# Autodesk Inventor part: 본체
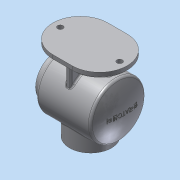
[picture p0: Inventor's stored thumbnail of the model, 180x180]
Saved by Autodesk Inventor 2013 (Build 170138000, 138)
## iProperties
Created: 2016-04
Part Number: 본체
Material: 알루미늄 6061
Document SubType Name: Modeling
Designer: dgall
Density: 2.71 g/cm^3
Mass: 909.634 g
Surface Area: 1226.76 cm^2
Volume: 335.658 cm^3
Author: dgall
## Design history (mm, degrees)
sketch "스케치1"
  geometry: L1 (-61, 0)-(61, 0); L2 (-61, 27)-(-46, 27); L3 (-46, 27)-(-46, 47); L4 (-46, 47)-(48.145, 47); L5 (-61, 27)-(-61, 38); L6 (-61, 38)-(-49, 38); L7 (-49, 38)-(-49, 50); L8 (-49, 50)-(50.087, 50); A1 r 120 centre (-59, 0) between (61, 0) and (50.087, 50); A2 r 117 centre (-59, 0) between (58, 0) and (48.145, 47); 2 further points
  constraints: 16 end point, 4 parallel, 4 point on circle, 3 perpendicular, 2 centre point, 2 point on line, 1 coincident, 1 concentric, 1 horizontal, 1 horizontal alignment, 1 midpoint, 1 vertical alignment
  dimensions: "d0" = 122 distance of L1.end L1.start; "d11" = 54 diameter of L2 L1; "d12" = 76 diameter of L6 L1; "d13" = 100 diameter of L8 L1; "d14" = 94 diameter of L4 L1; "d16" = 3 distance between parallel lines of L3 L7; "d99" = 120 radius of A1; "d101" = 3 distance of L1.end A2.start
revolve "회전1" sketch "스케치1" stored, may be unused: angle "d18" = 90 deg
node "작업 평면1"
sketch "스케치2"
  geometry: L1 (49.544, 50)-(49.544, -50) reference; C1 r 38 at (-0.456, 0); 1 further point
  constraints: 1 centre point, 1 horizontal alignment
  dimensions: "d104" = 50 distance from line of L1 C1.centre; "d105" = 76 diameter of C1
extrude "돌출1" join sketch "스케치2" distance "d23" = 15; taper "d25" = 0 deg; dims "d24" = 30, "d26" = 0
sketch "스케치13"
  geometry: L1 (61, 27)-(61, -27) reference; L2 (46, 47)-(46, -47) reference; L3 (-48.145, -47)-(46, -47) reference; L4 (61, 0)-(-58, 0); L5 (46, 0)-(46, -47); L6 (46, -47)-(-48.145, -47); A1 r 117 centre (59, 0) between (-48.145, 47) and (-48.145, -47) reference; A2 r 117 centre (59, 0) between (-58, 0) and (-48.145, -47); 1 further point
  constraints: 6 end point, 3 point on circle, 2 collinear, 2 midpoint, 1 centre point, 1 concentric, 1 point on line
revolve "회전4" sketch "스케치13" stored, may be unused: angle "d102" = 90 deg
node "작업 평면2"
sketch "스케치5"
  geometry: L1 (-17.5, 50)-(17.5, 50); L2 (-17.5, -50)-(17.5, -50); C1 r 5 at (54, 0); C2 r 5 at (-54, 0); A1 r 50 centre (-17.5, 0) between (-17.5, 50) and (-17.5, -50); A2 r 50 centre (17.5, 0) between (17.5, -50) and (17.5, 50); 1 further point
  constraints: 4 centre point, 4 end point, 4 horizontal alignment, 4 point on circle, 2 equal radius, 2 tangent, 1 horizontal, 1 parallel
  dimensions: "d34" = 135 dimension on A2 A1; "d36" = 50 radius of A1; "d37" = 17.5 distance of point (0, 0) A2.centre; "d38" = 10 diameter of C1; "d39" = 54 distance of point (0, 0) C1.centre; "d40" = 54 distance of C2.centre point (0, 0)
extrude "돌출3" join sketch "스케치5" distance "d41" = 10; taper "d42" = 0 deg
node "작업 평면3"
  node "작업축2"
sketch "스케치6"
  geometry: L1 (-49.544, -50)-(49.544, -50) reference; L2 (-18.044, -69)-(-68.044, -69) reference; L3 (66.956, -69)-(16.956, -69) reference; L4 (16.956, -69)-(-18.044, -69) reference; L5 (-68.044, -79)-(-68.044, -69) reference; L6 (66.956, -79)-(66.956, -69) reference; L7 (-39.544, -69)-(-36.193, -50); L8 (40.456, -69)-(37.106, -50); L9 (38.456, 65)-(-37.544, 65) reference; 1 further point
  constraints: 4 end point, 4 point on line, 1 equal length
  dimensions: "d44" = 39 horizontal distance of point (-0.544, 0) L7.start; "d45" = 41 horizontal distance of L8.start point (-0.544, 0); "d46" = 100 deg angle of L3 L8
sketch "스케치7"
  geometry: L1 (-50, 69)-(50, 69) reference; L2 (-40, 30)-(-40, 69); L3 (40, 30)-(40, 69); A1 r 50 centre (0, 0) between (-40, 30) and (40, 30) reference; 1 further point
  constraints: 4 end point, 2 point on circle, 2 point on line, 1 horizontal alignment, 1 parallel, 1 perpendicular
  dimensions: "d47" = 40 distance from line of point (0, 0) L2
extrude "돌출4" join sketch "스케치7" stored distance "d48" = 10; taper "d49" = 0 deg
feature "리브1" dims "d50" = 1, "d51" = 10, "d52" = 0, "d53" = 0, "d54" = 1, "d55" = 1
feature "리브2" dims "d56" = 1, "d57" = 10, "d58" = 0, "d59" = 0, "d60" = 1, "d61" = 1
chamfer "모따기1" distance "d62" = 3; stored, may be unused: second distance "d63" = 2, angle "d64" = 45 deg
fillet "모깎기3" dims "d65" = 5
fillet "모깎기5" dims "d67" = 2
chamfer "모따기2" distance "d68" = 1; stored, may be unused: second distance "d69" = 2, angle "d70" = 45 deg
sketch "스케치8"
  geometry: C1 r 38 at (0, 0) reference; 1 further point
  constraints: 1 horizontal alignment
  dimensions: "d71" = 32.5 distance of C1.centre point (-32.5, 0)
hole "구멍1" sketch "스케치8" at (-32.5, 0) diameter "d72" = 3.242; stored, may be unused: countersink angle "d76" = 90 deg, drill point angle "d78" = 118 deg; dims "d73" = 8, "d74" = 4, "d75" = 2, "d77" = 10
fillet "모깎기6" dims "d93" = 3
fillet "모깎기7" dims "d94" = 3
fillet "모깎기8" dims "d95" = 3
fillet "모깎기9" dims "d103" = 2
node "작업 평면5"
sketch "스케치15"
  geometry: C1 r 38 at (0, 0) reference; C2 r 27 at (0, 0); 1 further point
  constraints: 1 centre point, 1 concentric
  dimensions: "d106" = 54 diameter of C2
extrude "돌출5" cut sketch "스케치15" distance "d108" = 30; taper "d109" = 0 deg
chamfer "모따기3" distance "d110" = 1; stored, may be unused: second distance "d111" = 2, angle "d112" = 45 deg
fillet "모깎기10" dims "d113" = 3
sketch "스케치16"
  geometry: C1 r 38 at (0, 0) reference; 2 further points
  constraints: 1 vertical alignment
  dimensions: "d114" = 32.5 distance of point (0, 32.5) C1.centre
hole "구멍3" sketch "스케치16" at (0, 32.5) diameter "d115" = 3.242; stored, may be unused: countersink angle "d119" = 90 deg, drill point angle "d121" = 118 deg; dims "d116" = 8, "d117" = 4, "d118" = 2, "d120" = 10
node "작업 평면7"
  node "작업 평면6"
sketch "스케치17"
  geometry: 2 further points
  constraints: 1 coincident, 1 other
feature "엠보싱1" sketch "스케치17" dims "d0" = 122, "d34" = 135, "d36" = 50, "d37" = 17.5, "d38" = 10, "d39" = 54, "d40" = 54, "d126" = 0.5, "d127" = 0.5 deg
node "솔리드1"
pattern_circular "원형 패턴1" dims angle "d80" = 360 deg
pattern_circular "원형 패턴3" dims angle "d123" = 360 deg
other parameters: "d32" = 79, "d43" = 0, "d125" = -2
